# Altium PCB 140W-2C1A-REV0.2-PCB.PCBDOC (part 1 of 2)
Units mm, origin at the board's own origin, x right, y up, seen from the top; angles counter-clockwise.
Board outline 106.75 x 106.95 mm, 4 copper layers (Top Layer, MidLayer1, MidLayer2, Bottom Layer); 108 components, 173 nets, 312 pads, 723 vias.
Unrouted connection lines stored in the file: 15.
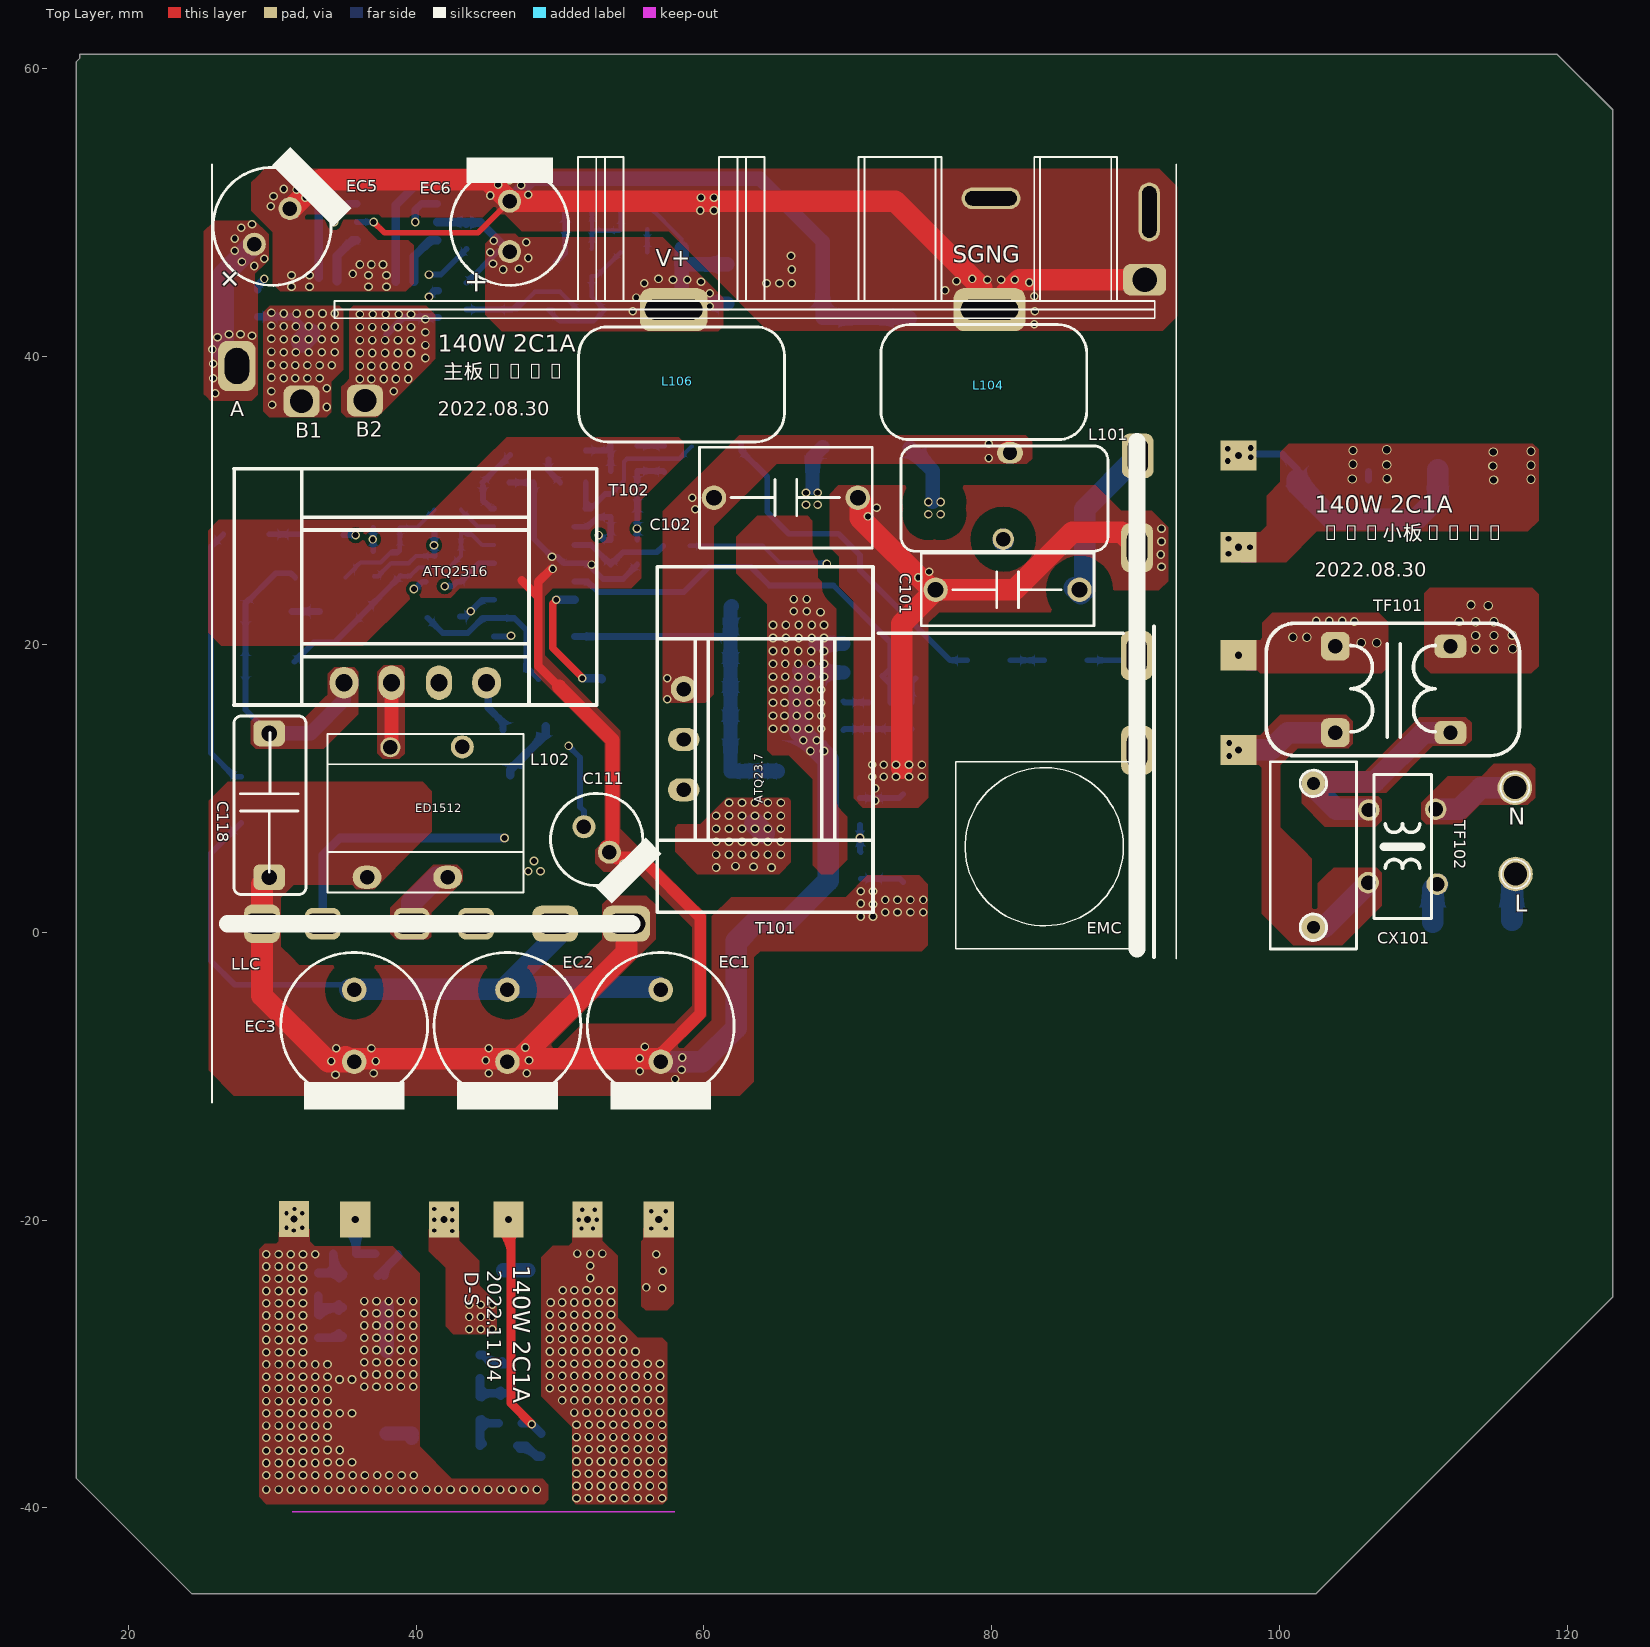
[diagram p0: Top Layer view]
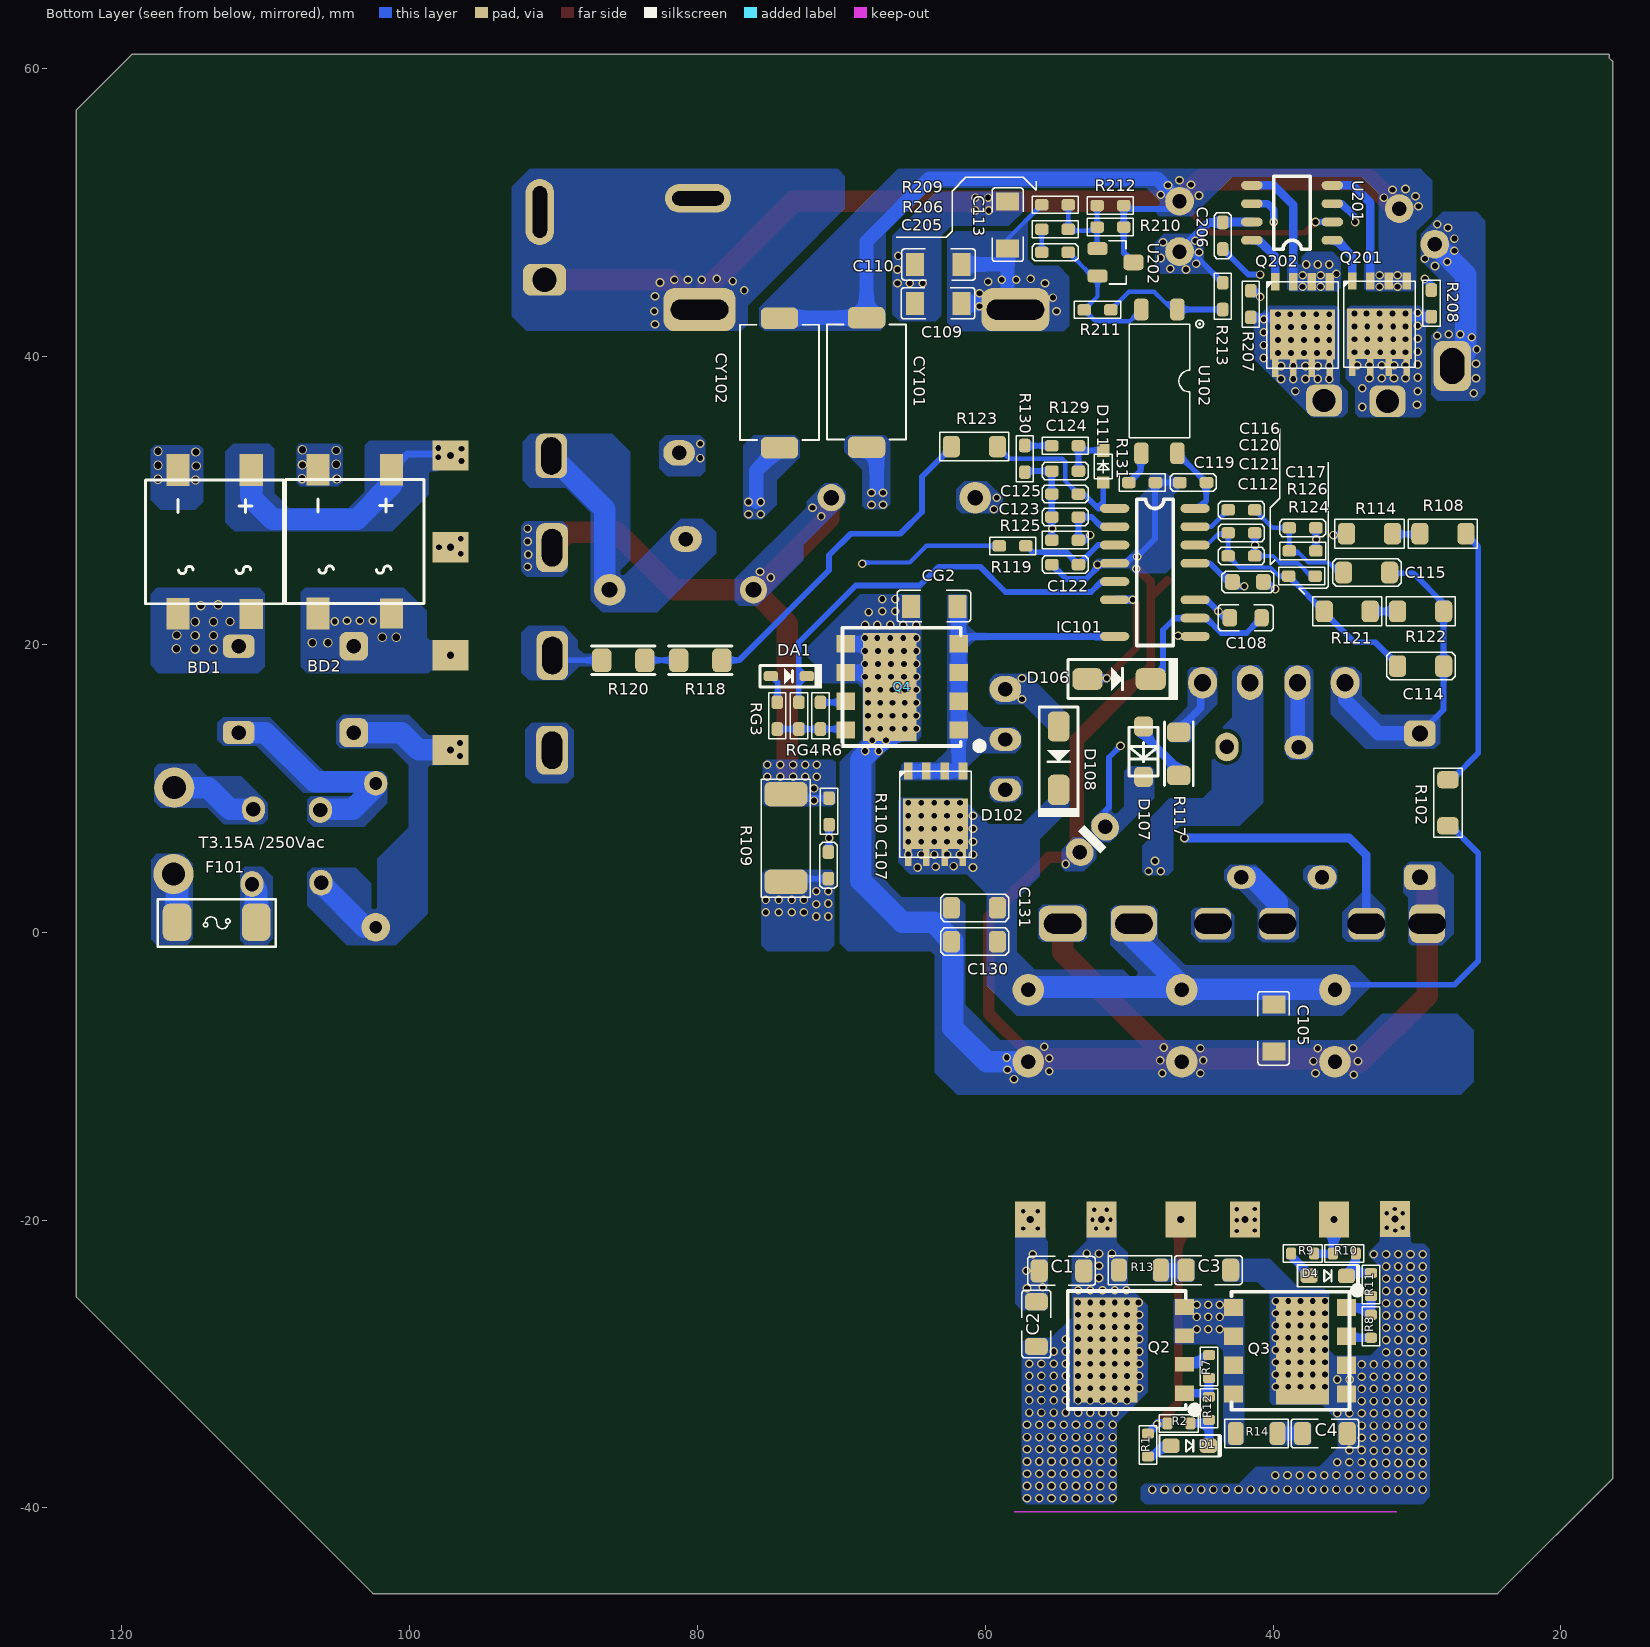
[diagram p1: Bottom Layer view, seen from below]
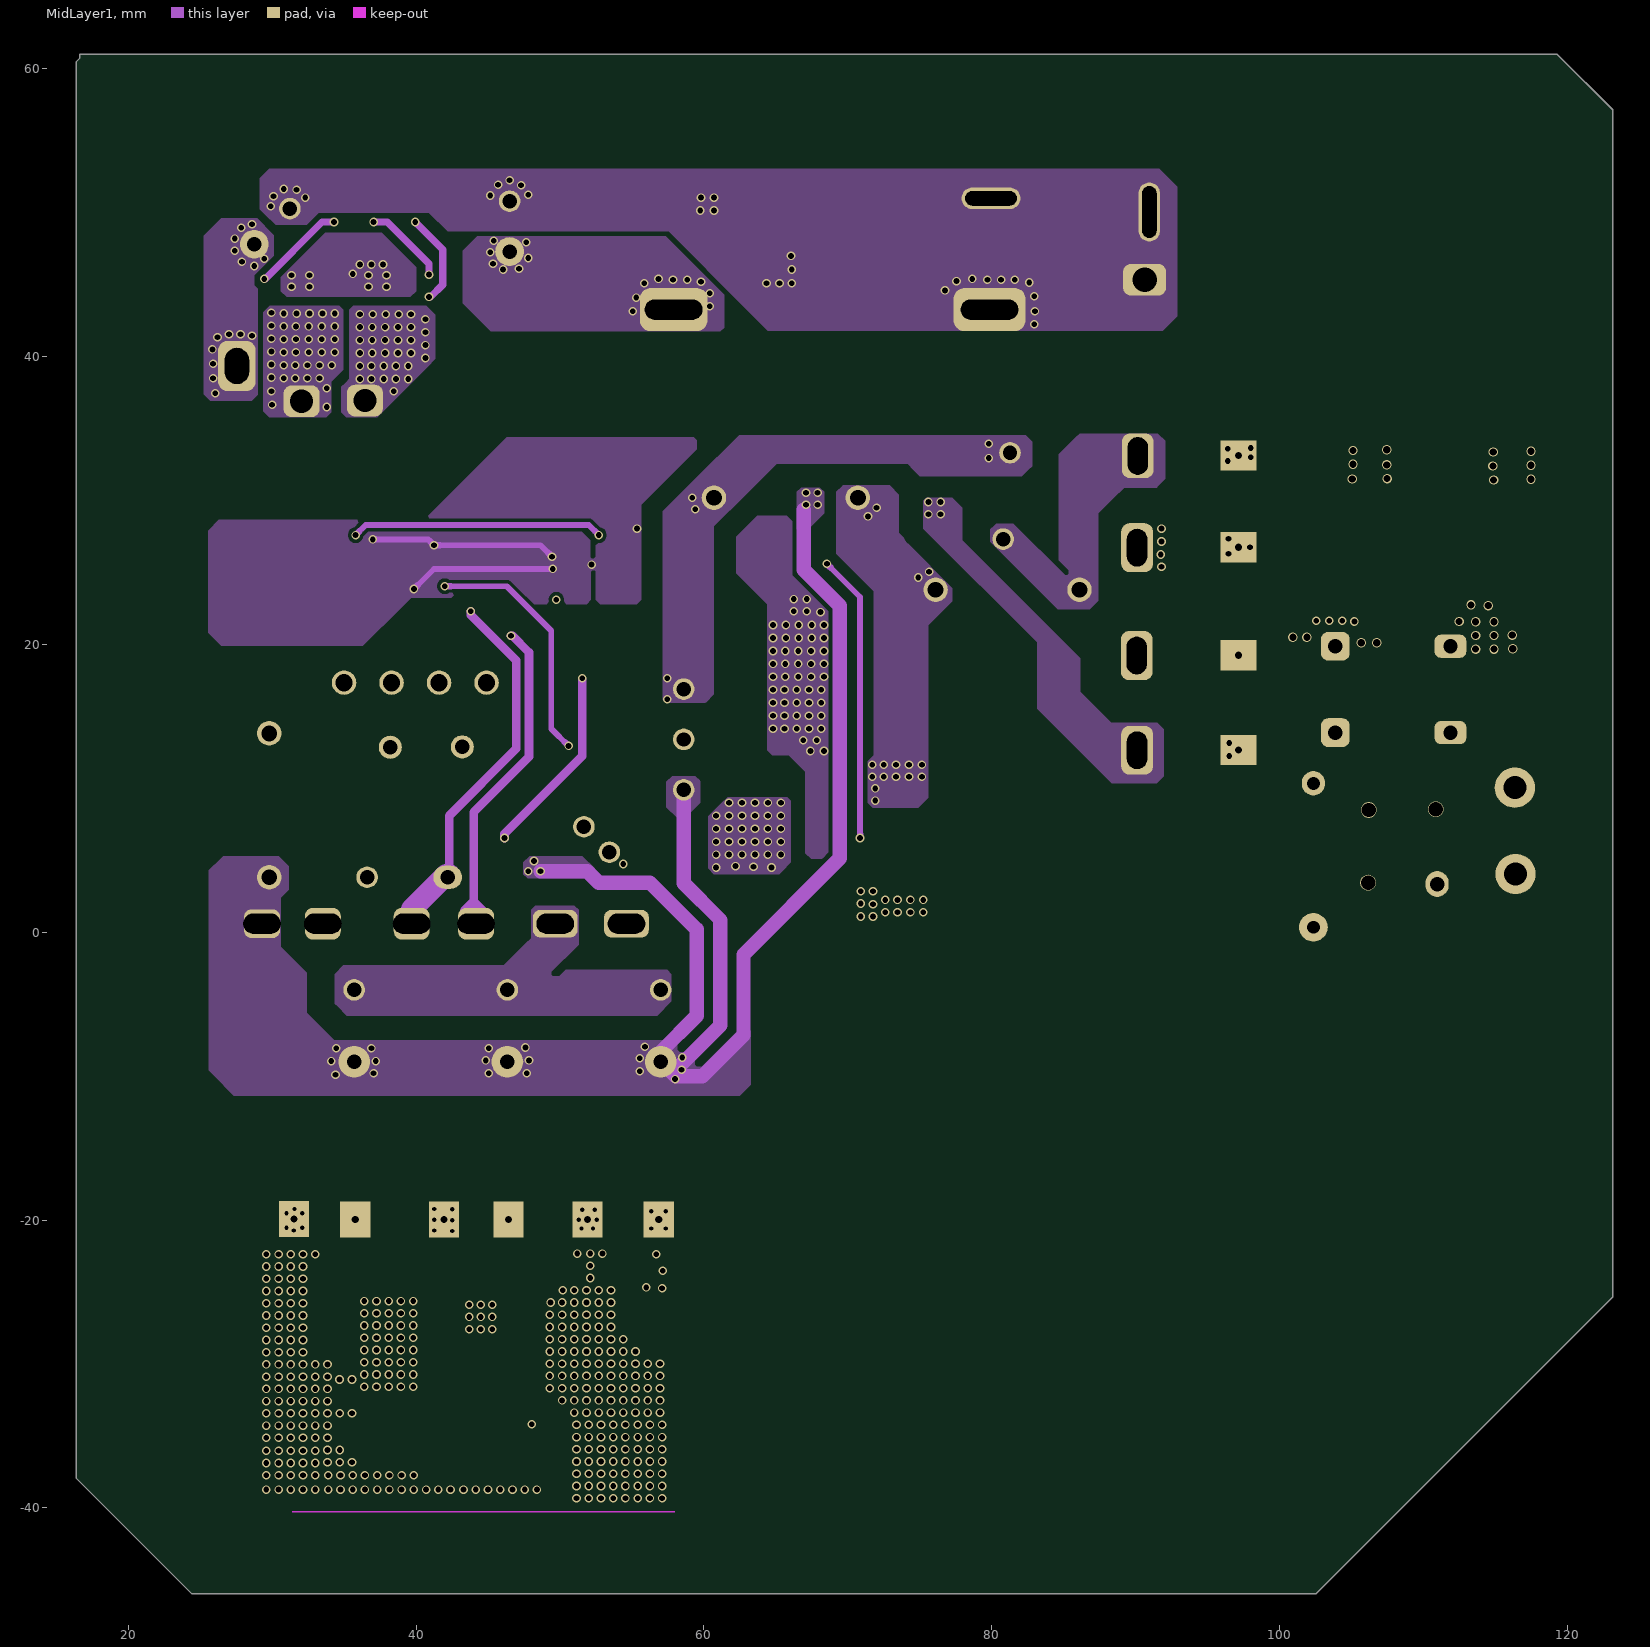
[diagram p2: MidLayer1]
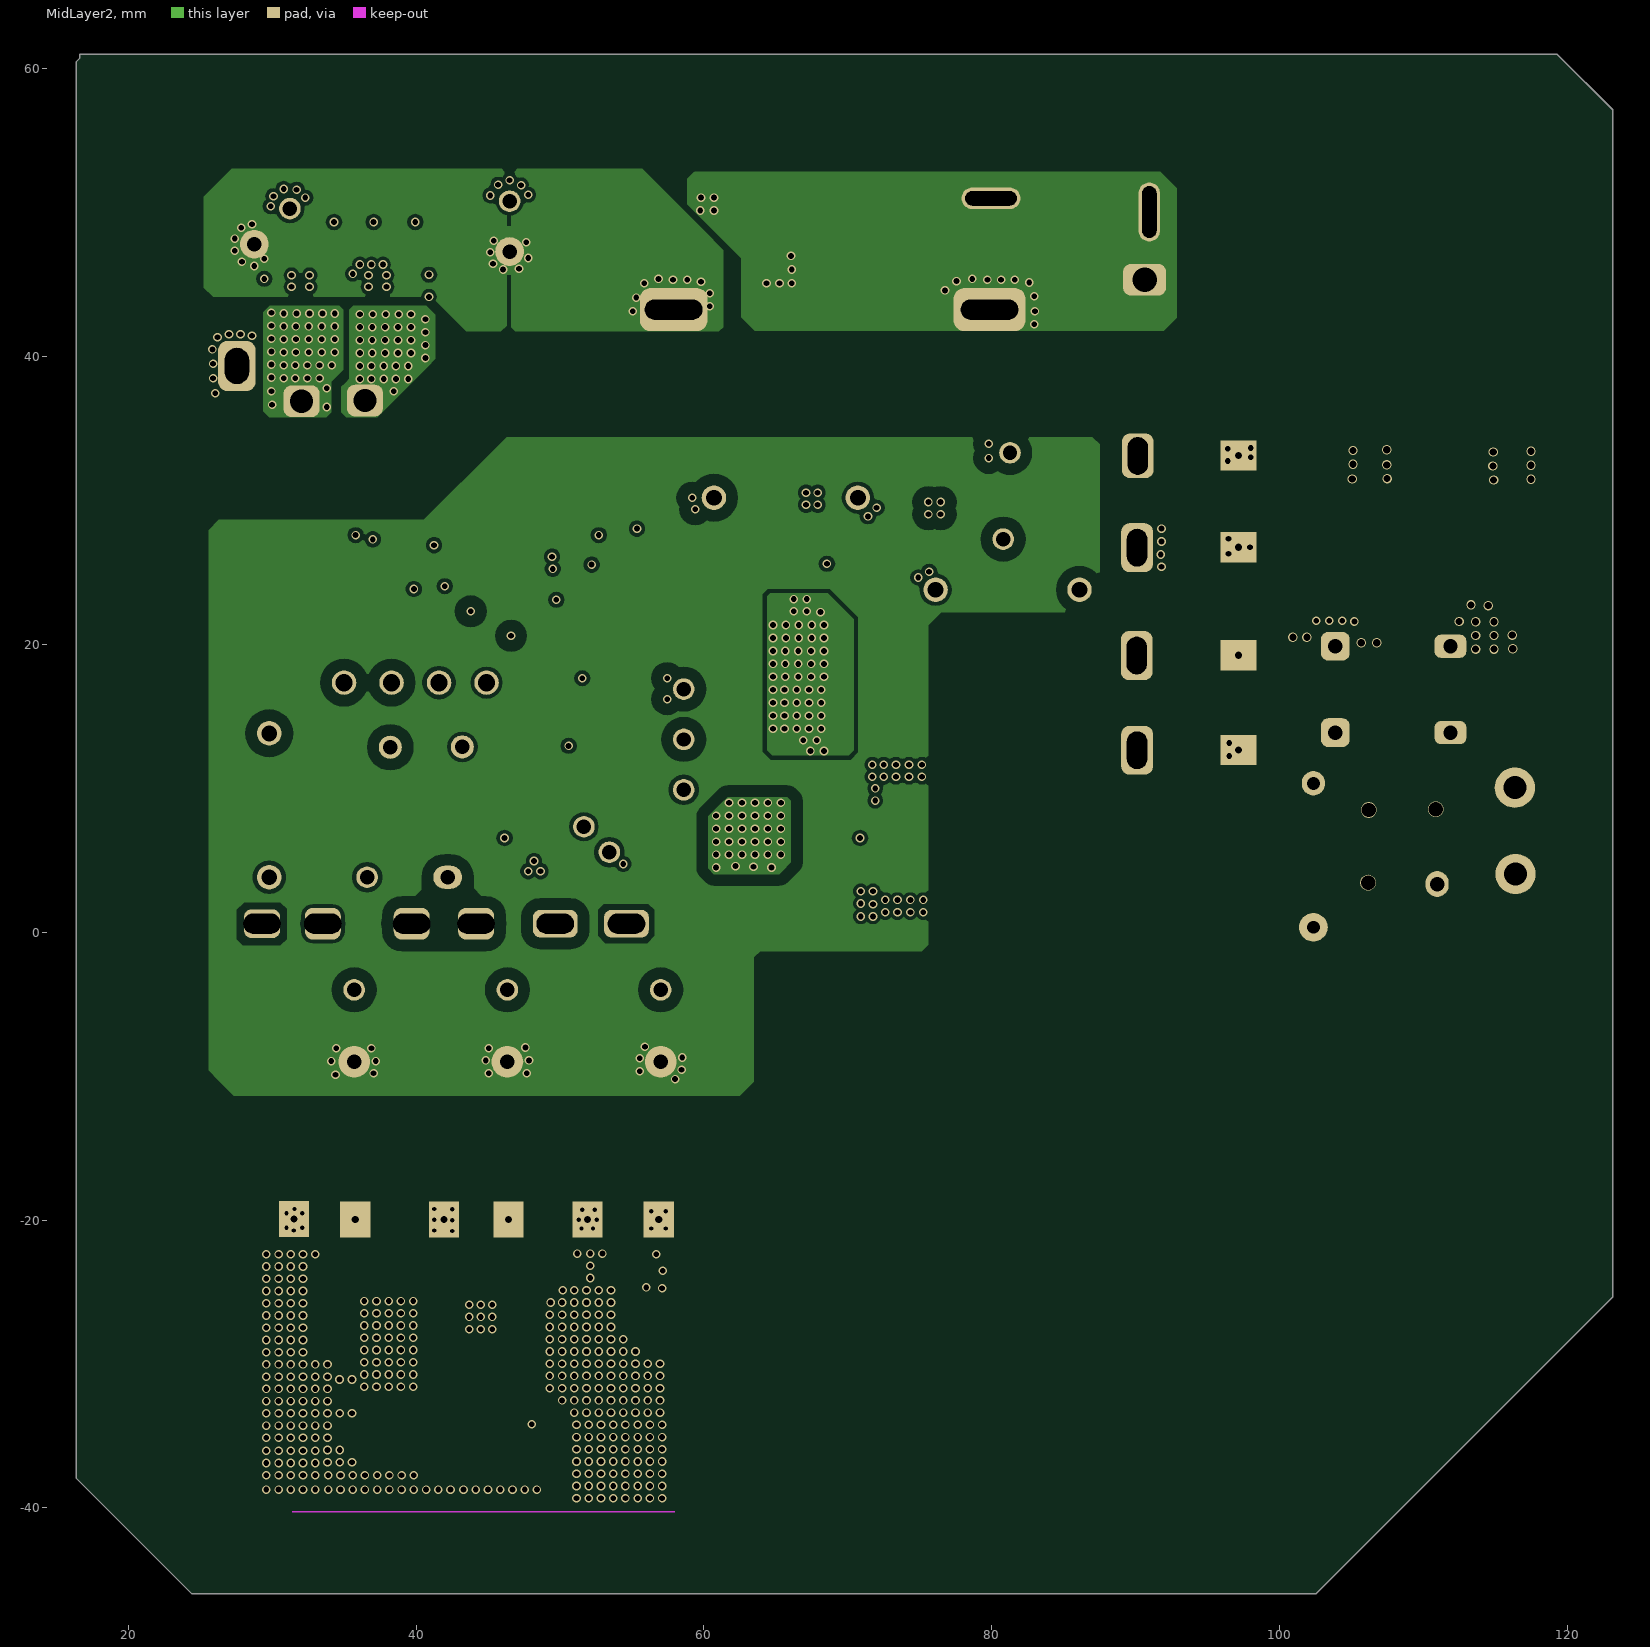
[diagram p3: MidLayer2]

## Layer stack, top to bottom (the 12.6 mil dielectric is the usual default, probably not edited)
Top Solder: solder mask 0.0102, Solder Resist, Dk 3.5
Top Layer: signal copper 0.0356
Dielectric1: core 0.32, FR-4, Dk 4.8
MidLayer1: signal copper 0.0356
Dielectric2: prepreg 0.32, FR-4, Dk 4.8
MidLayer2: signal copper 0.0356
Dielectric3: core 0.32, FR-4, Dk 4.8
Bottom Layer: signal copper 0.0356
Bottom Solder: solder mask 0.0102, Solder Resist, Dk 3.5

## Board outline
16.65,61 119.3,61 123.15,57.15 123.15,-25.35 102.55,-45.95 24.4,-45.95 16.4,-37.95 16.4,60.5 16.65,60.75
cut-out: -672.841,-265.044 -672.587,-265.044 -672.587,-264.79 -672.841,-264.79

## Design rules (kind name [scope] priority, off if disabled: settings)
Clearance Clearance_5 [InNet('NetBD101_4') vs InNet('NetCX101_2')] p1: gap=1.5
Clearance Clearance_4 [InNet('NetBD101_1') vs InNet('NetBD101_4')] p2: gap=1.5
Clearance Clearance_3 [InNet('PGND') And OnLayer('MidLayer2') vs InNetClass('New Class')] p3: gap=0.8
Clearance Clearance_1 [InNet('PGND') And OnLayer('MidLayer1') vs InNetClass('New Class')] p4: gap=0.8
Clearance [InNet('PGND') And OnLayer('Top Layer') vs InNetClass('New Class')] p5: gap=1.2
Clearance Clearance_2 [All] p6: gap=0.25
ComponentClearance [All] p1 off: gap=0.254 collisioncheckmode=3 verticalgap=0.254 showdistances=FALSE
FabricationTestpoint [(IsPad And (OnTopLayer Or OnBottomLayer))] p1: side=3 testpointundercomponent=TRUE minsize=1.016 maxsize=2.54 preferedsize=1.524 minholesize=0 maxholesize=1.016 preferedholesize=0.813 testpointgrid=0.025 allowsidetop=TRUE allowsidebottom=TRUE usegrid=TRUE gridtolerance=0
Height [All] p1 off: minheight=0 maxheight=25.4 prefheight=12.7
HoleSize [All] p1: absolutevalues=TRUE maxlimit=6 minlimit=0.4 maxpercent=80.000 minpercent=20.000
PolygonConnect [All] p1: connectstyle=Direct reliefconductorwidth=0.254 reliefentries=4 polygonreliefangle="90 Angle" airgapwidth=0.254
RoutingVias [All] p1: holewidth=0.4 width=0.7 viastyle="Through Hole" minholewidth=0.4 minwidth=0.5 maxholewidth=0.6 maxwidth=0.8
SolderMaskExpansion [All] p1: expansion=0.075
Width [All] p1: maxlimit=10 minlimit=0.2 preferedwidth=0.4 midlayer1_minwidth=0.254 midlayer2_minwidth=0.254 bottomlayer_minwidth=0.3 minimp=50.000000 maximp=50.000000 favimp=50.000000
26 further rules are at their usual default settings.

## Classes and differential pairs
net class "New Class": GATEH NetBD1 NetBD101_1 NetC101_1 NetC101_2 NetC108_1 NetC114_1 NetCX101_2 NetD103_1 NetIC101_9 NetL102_2
component class TEA2016-AP-SCH: BD101 C104 C105 C107 C108 C111 C112 C114 C115 C116 C117 C118 C119 C120 C121 C122 C123 C124 C201 C202 C203 C204 C205 C206 C207 C208 C211 CN101 CY101 D101 D103 D105 D106 D107 D109 D110 D111 D201 D202 F101 Q101 Q103 Q201 Q202 R102 R103 R105 R106 R107 R108 R109 R110 R111 R112 R113 R114 R115 R116 R117 R118 R119 R121 R122 R123 R124 R125 R126 R127 R129 R130 R131 R133 R201 R202 R203 R204 R205 R206 R208 R209 R210 R211 R212 R213 R214 R215 R216 T101 T102 TF102 U102 U103 U202 Z201
pad class "New Class": Free-00

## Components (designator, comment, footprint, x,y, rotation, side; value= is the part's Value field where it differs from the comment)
BD1 "WRLSB80M" MB30M 113.55,27.125 r90 bottom
BD2 "WRLSB80M" MB30M 103.8,27.15 r90 bottom
C1 "223M/630V" 1206CH 54.698,-23.525 r0 bottom (schematic designator C105)
C2 "223M/630V" 1206CH 56.448,-27.225 r90 bottom (schematic designator C105)
C3 "223M/630V" 1206CH 44.498,-23.475 r0 bottom (schematic designator C105)
C4 "223M/630V" 1206CH 36.398,-34.825 r180 bottom (schematic designator C105)
C101 "474/450V" XC-12X6-P10#1 81.1,23.8 r0 top
C102 "474/450V" XC-12X6-P10#2 65.7,30.2 r0 top (schematic designator C101)
C105 "223M/630V" 1206C(W)#1 39.95,-6.65 r90 bottom
C107 "473" 0603C(W) 70.9,4.65 r90 bottom
C108 "334PM/50V" 0805C(W)#1 41.9,21.85 r180 bottom
C109 "103M/50V" 1206C(W)#1 63.269,43.689 r180 bottom (schematic designator C105)
C110 "103M/50V" 1206C(W)#1 63.269,46.414 r0 bottom (schematic designator C105)
C111 "47UF/50V" EC-6.5X11-P2.5-C 52.55,6.45 r315 top
C112 "104" 0805C(W)#2 41.75,24.35 r180 bottom
C113 "103M/50V" 1206C(W)#1 58.45,49.15 r270 bottom (schematic designator C105)
C114 "1KV/33P" 1206C(W)#2 29.75,18.5 r0 bottom
C115 "1KV/102PK" 1206C(W)#2 33.5,25 r0 bottom
C116 "222PK/50V" 0603C(W) 42.2,29.35 r0 bottom
C117 "103PK/50V" 0603C(W) 37.95,28.1 r0 bottom
C118 "MMKP82/333J/630V" MC-15.5X6.5-P12.5 29.847,7.723 r90 top
C119 "NC" 0603C(W) 45.55,31.25 r0 bottom
C120 "103" 0603C(W) 42.2,27.75 r0 bottom
C121 "102" 0603C(W) 42.2,26.15 r0 bottom
C122 "1nF" 0603C(W) 54.45,25.55 r180 bottom
C123 "561PJ" 0603C(W) 54.45,28.85 r180 bottom
C124 "561" 0603C(W) 54.45,32.05 r180 bottom
C125 "100PJ/50V" 0603C(W) 54.45,30.45 r180 bottom (schematic designator C124)
C130 "223M/630V" 1206C(W)#2 60.75,-0.65 r0 bottom (schematic designator C105)
C131 "223M/630V" 1206C(W)#2 60.75,1.7 r0 bottom (schematic designator C105)
C205 "104PM" 0603C(W) 55.15,47.25 r0 bottom
C206 "104PM" 0603C(W) 43.5,48.4 r270 bottom (schematic designator C205)
CG2 "223M/630V" 1206C(W)#1 63.55,22.65 r180 bottom (schematic designator C105)
CX101 "474PM/275V" "CX-5*13  P=10mm" 102.35,5.35 r270 top
CY101 "1nF/400Vac" "1808 Y-Cap" 68.647,38.248 r270 bottom (schematic designator CY3)
CY102 "1nF/400Vac" "1808 Y-Cap" 74.697,38.223 r270 bottom (schematic designator CY3)
D1 "NC" 323 45.798,-35.675 r0 bottom (schematic designator D4)
D4 "NC" 323 36.198,-23.875 r0 bottom
D102 "600V/4A SIC" DFN5*6-8L 61.55,11.2 r0 bottom
D106 "RS2M" SMD-(DO-214AC/SMA)(H) 50.7,17.6 r180 bottom (schematic designator D2)
D107 "FR107" SOD-80 49,12.55 r270 bottom
D108 "S3M" SMD-(DO-214AC/SMA)(H) 54.9,12.1 r270 bottom (schematic designator D106)
D111 "1N4148(0805)" SOD-323 51.8,31.25 r180 bottom (schematic designator D4)
DA1 "1N4148" SMD-(SOD-323)(H) 73.65,17.8 r180 bottom
EC1 "22UF/450V 8X17" EC-10X18-P5-C 57,-6.5 r270 top (schematic designator CD3)
EC2 "450V/22UF 10*17" EC-10X18-P5-C 46.35,-6.5 r270 top
EC3 "22UF/450V 8X17" EC-10X18-P5-C 35.7,-6.5 r270 top (schematic designator CD3)
EC5 "Comment" EC-8X12-P3.5-C 30,49.05 r45 top
EC6 "Comment" EC-8X12-P3.5-C 46.5,49.05 r90 top
EMC "Comment" 无桥整流 90.1,-0.275 r90 top locked
F101 "T3.15A /250Vac" F-6125 113.4,0.7 r0 bottom
IC101 "TEA2016/SOP-16" SO-16 51,29.45 r180 bottom (schematic designator U1)
L101 "200UH" L10*6*5#1 80.622,30.548 r270 top
L102 "ED1512" ED1512 40.7,3.825 r90 top locked
L104 "T12/6/5/20UH" L10*6*5#2 79.75,38 r90 top
L106 "T12/6/5/20UH" L10*6*5#2 58.15,38.3 r270 top
LLC "Comment" LLC 54.622,0.598 r180 top locked
Q2 "Comment" IPL60R365P7-Cascode-DFN8X8 48.898,-29.025 r90 bottom
Q3 "Comment" "Cascode-DFN8X8 - new" 38.848,-29.075 r270 bottom
Q4 "Comment" "Cascode-DFN8X8 - new" 65.75,17.05 r90 bottom
Q201 "60V/4mR" DFN5*6-8L 30.7,45.25 r0 bottom
Q202 "60V/4mR" DFN5*6-8L 36.05,45.2 r0 bottom
R1 "NC" 0603RH 48.698,-35.625 r90 bottom (schematic designator R103)
R2 "300R" 0603RH 46.548,-34.125 r0 bottom (schematic designator R105)
R6 "300R" 0603R 71.45,15.05 r270 bottom (schematic designator R105)
R7 "10K" 0603RH 44.448,-30.175 r270 bottom (schematic designator R133)
R8 "10K" 0603RH 33.198,-27.375 r90 bottom (schematic designator R133)
R9 "NC" 0603RH 37.948,-22.325 r180 bottom (schematic designator R111)
R10 "300R" 0603RH 35.048,-22.325 r0 bottom (schematic designator R112)
R11 "300R" 0603RH 33.198,-24.475 r90 bottom (schematic designator R112)
R12 "300R" 0603RH 44.448,-33.075 r270 bottom (schematic designator R112)
R13 "300R" 1206RH 49.248,-23.475 r180 bottom (schematic designator R112)
R14 "300R" 1206RH 41.148,-34.825 r180 bottom (schematic designator R112)
R102 "750K" 1206(W) 27.85,9 r270 bottom
R108 "7.5M" 1206(W) 28.2,27.7 r180 bottom
R109 "0.068R" 2512(W) 73.85,6.55 r90 bottom
R110 "2.7R" 0603(W) 70.85,8.4 r270 bottom
R114 "7.5M" 1206(W) 33.3,27.7 r180 bottom
R117 "4.7R" 1206 46.55,13.9 r270 bottom
R118 "10M" 1206 78.3,18.9 r0 bottom
R119 "100R" 0603(W) 58.1,26.85 r180 bottom
R120 "10M" 1206 83.65,18.9 r0 bottom (schematic designator R118)
R121 "1M5" 1206(W) 34.85,22.3 r0 bottom
R122 "1M3" 1206(W) 29.75,22.3 r0 bottom
R123 "10M" 1206(W) 60.75,33.75 r180 bottom
R124 "20K" 0603(W) 38,24.75 r0 bottom
R125 "1K" 0603(W) 54.45,27.25 r180 bottom
R126 "13R3" 0603(W) 37.95,26.5 r0 bottom
R129 "20K" 0603(W) 54.45,33.8 r180 bottom
R130 "NTC/100K" 0603(W) 57.25,32.9 r270 bottom
R131 "1K" 0603(W) 49.1,31.25 r0 bottom
R206 "47K" 0603R 55.15,48.85 r180 bottom
R207 "20R" 0603R 41.55,43.65 r90 bottom (schematic designator R206)
R208 "20R" 0603R 29,43.7 r90 bottom (schematic designator R206)
R209 "68K 1%" 0603R 55.15,50.55 r180 bottom
R210 "680K 1%" 0603R 51.3,49 r0 bottom
R211 "1K" 0603R 52.2,43.25 r180 bottom
R212 "9K31 1%" 0603R 51.3,50.5 r0 bottom
R213 "3K" 0603R 43.5,44.2 r90 bottom
RG3 "10R" 0603R 74.45,15.05 r90 bottom (schematic designator R22)
RG4 "390R" 0603R 72.95,15.05 r90 bottom (schematic designator R22)
T101 "ATQ23.7" ATQ23.7 64.25,13.4 r0 top locked
T102 "ATQ2516" ATQ25 34.997,17.348 r0 top locked
TF101 "TD1212-8MH" TD-1212-15MH 107.875,16.875 r0 top
TF102 "T9/5/3/600UH/0.5/8TS" 9*5*3 108.55,5.95 r270 top
U102 "CT1019" W_SO-4(P10)__EL1019 47.9,38.25 r270 bottom
U201 "TEA1995" SO-8 35.9,48.1 r0 bottom
U202 "Comment" SOT-23 50.95,46.55 r270 bottom

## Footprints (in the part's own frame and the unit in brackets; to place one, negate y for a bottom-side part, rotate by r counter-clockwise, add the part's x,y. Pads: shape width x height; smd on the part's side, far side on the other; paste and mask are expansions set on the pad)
9*5*3 [mm]
  round 1.5 / inner round 1.1 / far side oval 1.8x1.6 hole 1: 1(-2.6,2.3) 3(2.5,-2.4) 4(-2.55,-2.35)
  round 1.5 / inner oval 1.8x1.6 / far side oval 1.8x1.6 hole 1: 2(2.6,2.4)
  silkscreen extent -5,-2 5,2
323 [mm]
  rrect50% 1.2x1 smd mask+0.03: 1(1.3,0) 2(-1.3,0)
  silkscreen extent -2.25,-0.75 2.1,0.75, body extent -1.3,-0.65 1.3,0.65, height 1
0603(W) [mm]
  rrect50% 0.95x0.8 smd mask+0.03: 1(-0.925,0) 2(0.925,0)
  silkscreen extent -1.6,-0.6 1.6,0.6, body extent -0.77,-0.42 0.78,0.43, height 0.45
0603C(W) [mm]
  rrect50% 0.95x0.8 smd mask+0.03: 1(-0.925,0) 2(0.925,0)
  silkscreen extent -1.6,-0.6 1.6,0.6, body extent -0.8,-0.4 0.8,0.4, height 0.8
0603R [mm]
  rrect50% 0.95x0.8 smd mask+0.03: 1(-0.925,0) 2(0.925,0)
  silkscreen extent -1.6,-0.6 1.6,0.6, body extent -0.77,-0.42 0.78,0.43, height 0.45
0603RH [mm]
  rrect50% 0.7x0.85 smd mask+0.03: 1(-0.8,0) 2(0.8,0)
  silkscreen extent -1.35,-0.6 1.35,0.6, body extent -0.77,-0.42 0.78,0.43, height 0.45
0805C(W)#1 [mm]
  rrect50% 1x1.2 smd: 1(-1.1,0) 2(1.1,0)
  silkscreen extent -1.9,-0.9 1.9,0.9
0805C(W)#2 [mm]
  rrect50% 1.05x1.1 smd mask+0.03: 1(-1.075,0) 2(1.075,0)
  silkscreen extent -1.8,-0.75 1.8,0.75, body extent -1,-0.62 1,0.63, height 0.6
1206 [mm]
  rrect50% 1.35x1.65 smd: 1(0,0) 2(3,0)
  silkscreen extent -0.7,-1 3.7,1
1206(W) [mm]
  rrect50% 1.2x1.5 smd mask+0.03: 1(-1.6,0) 2(1.6,0)
  silkscreen extent -2.4,-1 2.4,1, body extent -1.6,-0.8 1.6,0.8, height 0.55
1206C(W)#1 [mm]
  rect 1.25x1.6 smd: 1(-1.625,0) 2(1.625,0)
  silkscreen extent -2.58,-1.07 2.53,1.1
1206C(W)#2 [mm]
  rrect50% 1.2x1.5 smd mask+0.03: 1(-1.6,0) 2(1.6,0)
  silkscreen extent -2.4,-0.95 2.35,0.95, body extent -1.6,-0.8 1.6,0.8, height 0.79
1206CH [mm]
  rrect50% 1.2x1.6 smd mask+0.03: 1(-1.55,0) 2(1.55,0)
  silkscreen extent -2.35,-1 2.35,1, body extent -1.6,-0.8 1.6,0.8, height 0.79
1206RH [mm]
  rrect50% 1.1x1.6 smd mask+0.03: 1(-1.45,0) 2(1.45,0)
  silkscreen extent -2.2,-1 2.2,1, body extent -1.6,-0.8 1.6,0.8, height 0.55
"1808 Y-Cap" [mm]
  rrect50% 1.5x2.6 smd: 1(-4.45,0.4) 2(4.55,0.4)
  silkscreen extent -3.99,-2.35 4.01,3.15
2512(W) [mm]
  rrect50% 1.7x3 smd mask+0.03: 1(-3.05,0) 2(3.05,0)
  silkscreen extent -4.1,-1.7 4.1,1.7, body extent -3.05,-1.6 3.35,1.6, height 0.6
ATQ23.7 [mm]
  round 1.8 / inner round 1.5 / far side oval 2.2x1.8 hole 1: 1(-5.65,3.5)
  oval 2.2x1.6 / inner round 1.5 / far side oval 2.2x1.6 hole 1: 2(-5.65,0) 3(-5.65,-3.5)
  silkscreen extent -7.5,-12 7.5,12
ATQ25 [mm]
  oval 2x2.2 / inner round 1.7 / far side oval 2x2.2 hole 1.2: 1(0,0) 4(9.9,0)
  oval 1.8x2.4 / inner round 1.7 / far side oval 1.8x2.4 hole 1.2: 2(3.3,0) 3(6.6,0)
  silkscreen extent -7.65,-1.55 17.55,14.85
"Cascode-DFN8X8 - new" [mm]
  rect 1.2x1.3 smd: D(-3,-3.9) D(-1,-3.9) D(1,-3.9) D(3,-3.9) G(-3,3.95) S(-1,3.95) S(1,3.95) S(3,3.95)
  rect 7.5x3.7 smd: S(0,0.887)
  silkscreen extent -4.45,-4.04 4.1,4.95
"CX-5*13  P=10mm" [mm]
  oval 1.7x1.6 hole 0.9: 1(-5,0)
  round 2 hole 0.9: 2(5,0)
  silkscreen extent -6.5,-3 6.5,3
DFN5*6-8L [mm]
  rect 0.6x1.2 smd: 1S(0,0) 2S(1.27,0) 3S(2.54,0) 4G(3.81,0)
  rect 0.45x1.2 smd: 5D(3.81,6) 6D(2.54,6) 7D(1.27,6) 8D(0,6)
  rect 4.5x3.5 smd: 9D(1.9,3.66)
  silkscreen extent -0.59,0 4.41,6
EC-6.5X11-P2.5-C [mm]
  round 1.6 / inner round 1.5 / far side oval 1.8x2 hole 1 mask+0.03: 1(-1.25,0) 2(1.25,0)
  silkscreen extent -3.2,-3.2 3.9,3.2, body extent -3.18,-3.18 3.18,3.18, height 11.33
EC-8X12-P3.5-C [mm]
  round 1.6 / inner round 2 / far side round 2 hole 1 mask+0.03: 1(-1.75,0)
  round 1.6 / inner round 1.5 / far side round 2 hole 1 mask+0.03: 2(1.75,0)
  silkscreen extent -4.1,-4.1 4.8,4.1, body extent -4.1,-4.1 4.1,4.1, height 13.1
EC-10X18-P5-C [mm]
  round 1.7 / inner round 1.5 / far side round 2.2 hole 1 mask+0.03: 1(-2.5,0)
  round 1.7 / inner round 2.2 / far side round 2.2 hole 1 mask+0.03: 2(2.5,0)
  silkscreen extent -5.1,-5.1 5.8,5.1, body extent -5.1,-5.1 5.1,5.1, height 19.05
ED1512 [mm]
  oval 1.6x2 hole 1: 1(0,-1.5)
  oval 1.6x2 / inner round 1.5 / far side oval 1.6x2 hole 1: 2(0,4.1)
  round 1.4 / inner round 1.6 / far side oval 1.6x2 hole 1: 3(9.033,2.487)
  round 1.6 / inner round 1.6 / far side oval 2x1.6 hole 1: 4(9.058,-2.513)
  silkscreen extent -1.05,-6.76 9.95,6.84
F-6125 [mm]
  rrect50% 2x2.6 smd mask+0.03: 1(-2.75,0) 2(2.75,0)
  silkscreen extent -4.1,-1.6 4.1,1.7
IPL60R365P7-Cascode-DFN8X8 [mm]
  rect 7.3x4.45 smd: D(0,2.737)
  rect 1.1x1.3 smd: G(-3,-2.737) S(3,-2.737)
  rect 1x1.3 smd: S(-1,-2.737) S(1,-2.737)
  silkscreen extent -4.4,-3.7 4.1,5.36, body extent -4.05,-2.8 4.05,5.3, height 1.1
L10*6*5#1 [mm]
  round 1.5 / inner round 1.5 / far side oval 1.8x2.2 hole 1: 0(3.229,0.175)
  oval 1.5x1.8 / inner round 1.5 / far side oval 1.8x2.2 hole 1: 1(-2.771,0.65)
  silkscreen extent -3.25,-6.93 4.08,7.45
L10*6*5#2 [mm]
  silkscreen extent -3.77,-6.85 4.23,7.45
LLC [mm]
  rrect50% 3.3x2.5 / inner rrect50% 3.1x1.9 / far side rrect50% 3.3x2.5 hole 1.4 slot 2.6 at 0 deg: 1(0,0)
  rrect50% 3.2x2.5 / inner rrect50% 3.1x1.9 / far side rrect50% 3.2x2.5 hole 1.4 slot 2.6 at 0 deg: 2(4.95,0)
  rrect50% 2.5x2.2 hole 1.4 slot 2.6 at 0 deg: 3(10.45,0) 4(14.925,0) 5(21.1,0)
  rrect50% 2.5x2.7 / inner rrect50% 2.5x2 / far side rrect50% 2.5x2.7 hole 1.4 slot 2.6 at 0 deg: 6(25.325,0)
  silkscreen extent -0.38,0 27.72,0
MB30M [mm]
  rect 2.2x1.6 smd: 1(-5,2.55) 3(5,-2.55) 4(5,2.55)
  rect 2.1x1.6 smd: 2(-5,-2.55)
  silkscreen extent -4.3,-4.8 4.3,4.8
MC-15.5X6.5-P12.5 [mm]
  rrect50% 1.8x2.2 / inner round 1.7 / far side rrect50% 1.8x2.2 hole 1.1 mask+0.03: 1(-3.9,0.05) 2(6.1,0.05)
  silkscreen extent -5.1,-2.5 7.3,2.5
SMD-(DO-214AC/SMA)(H) [mm]
  rrect50% 2.1x1.5 smd mask+0.03: 1(-2.2,0) 2(2.2,0)
  silkscreen extent -3.55,-1.45 4.1,1.45, body extent -2.3,-1.35 2.3,1.35, height 2.4
SMD-(SOD-323)(H) [mm]
  rrect50% 1x0.7 smd mask+0.03: 1(-1.25,0) 2(1.25,0)
  silkscreen extent -2,-0.85 2.3,0.85, body extent -1.3,-0.65 1.3,0.65, height 1
SO-8 [mm]
  oval 1.5x0.61 smd: 1GDB(-0.014,0.012) 2GND(-0.014,-1.257) 3DSB(-0.014,-2.527) 4SSB(-0.014,-3.797) 5SSA(5.573,-3.797) 6DSA(5.573,-2.527) 7VCC(5.574,-1.257) 8GDA(5.574,0.013)
  silkscreen extent 1.51,-4.43 4.05,0.65
SO-16 [mil]
  oval 80x24 smd: 1(-0.28,0) 2(-0.28,-50) 3(-0.28,-100) 4(-0.28,-150) 5(-0.28,-200) 6(-0.28,-250) 8(-0.28,-350) 9(219.72,-350) 10(219.72,-300) 11(219.72,-250) 13(219.72,-150) 14(219.72,-100) 15(219.72,-50) 16(219.72,0)
  oval 80x24 on Mech13: 7(-0.28,-300) 12(219.72,-200)
  silkscreen extent 60,-375 160,25, body extent -6,-371 230,23, height 72
SOD-80 [mm]
  rrect50% 1.4x1.3 smd: 1(-1.75,0) 2(1.75,-0.001)
  silkscreen extent -1.7,-1 1.7,1
SOD-323 [mm]
  rect 0.85x0.85 smd: A(0,0)
  rect 0.85x0.9 smd: K(0,2.23)
  silkscreen extent -0.63,0.26 0.63,1.97
SOT-23 [mm]
  rrect50% 0.9x1.4 smd mask+0.03: 1(-0.95,-1.25) 3(0.95,-1.25)
  rrect50% 1.1x1.4 smd mask+0.03: 2(0,1.25)
  silkscreen extent -1.5,-0.45 1.5,0.75, body extent -1.45,-1.4 1.45,1.4, height 1.2
TD-1212-15MH [mm]
  rrect50% 2.2x1.6 hole 1: 0(4,3) 1(4,-3)
  rrect50% 2x2 hole 1: 2(-4,-3) 3(-4,3)
  silkscreen extent -8.8,-4.6 8.8,4.6
W_SO-4(P10)__EL1019 [mm]
  rrect50% 1.5x1 smd: 1(-5.025,1.25) 2(-5.025,-1.25) 3(4.975,-1.251) 4(4.975,1.25)
  silkscreen extent -4.29,-2.1 3.9,3.07
XC-12X6-P10#1 [mm]
  round 1.7 / inner round 1.7 / far side round 1.9 hole 1.1 mask+0.03: 1(-5,0)
  round 1.7 / inner round 1.7 / far side round 2.2 hole 1.1 mask+0.03: 2(5,0)
  silkscreen extent -6,-2.5 6,2.55
XC-12X6-P10#2 [mm]
  round 1.7 / inner round 1.7 / far side round 2.2 hole 1.1 mask+0.03: 1(-5,0)
  round 1.7 / inner round 1.7 / far side round 1.9 hole 1.1 mask+0.03: 2(5,0)
  silkscreen extent -6,-3.5 6,3.5
无桥整流 [mm]
  rrect50% 3.4x2.2 hole 1.4 slot 2.6 at 0 deg: 3(12.925,0) 4(19.5,0.025) 5(27,0)
  rrect50% 3.1x2.2 hole 1.4 slot 2.6 at 0 deg: 6(33.375,-0.05)
  silkscreen extent -0.87,0 34.37,11.95

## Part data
C1 C2 C3 C4 C105 C107 C108 C109 C110 C112 C113 C114 C115 C116 C117 C118 C119 C120 C121 C122 C123 C124 C125 C130 C131 C205 C206 CG2: library part Cap, "Capacitor"
C101 C102: library part CX, "CX"
CY101 CY102: library part Cap
D1 D4 D111: library part D
D106: library part Diode
D107 D108: library part Diode, "Default Diode"
EC1 EC3: library part CAP-E, "电解电容"
IC101: library part TEA1755T/SOP-16_1, "贴片IC"
R1 R2 R6 R7 R8 R9 R10 R11 R12 R13 R14 R102 R108 R109 R110 R114 R117 R118 R119 R120 R121 R122 R123 R124 R125 R126 R129 R131 R206 R207 R208 R209 R210 R211 R212 R213: library part Res2, "Resistor"
R130: library part "Res Adj1", "Variable Resistor"
RG3 RG4: library part 1/8WR

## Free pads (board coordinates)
  oval 4.1x1.5 / inner oval 4.1x1.5 / far side oval 4.6x2 hole 1 slot 3.6 at 0 deg: 0(79.95,51)
  rrect50% 3x2.2 hole 1.7: 0(90.625,45.342)
  oval 1.5x4.1 / inner oval 1.5x4.1 / far side oval 2x4.6 hole 1 slot 3.6 at 90 deg: 0(90.95,50.05)
  round 2.4 / inner round 2.8 / far side round 2.8 hole 1.6: 0(116.35,10.05) 0(116.4,4.05)
  rect 2.1x2.5 hole 0.5: 2(31.52,-19.925) 2(35.77,-19.95) 2(41.945,-19.95) 2(46.42,-19.95) 2(51.92,-19.95) 2(56.87,-19.95)
  rrect50% 4.7x3 hole 1.4 slot 4 at 0 deg: 2(57.9,43.267)
  rrect50% 5x3 hole 1.4 slot 4 at 0 deg: 2(79.85,43.267)
  rect 2.5x2.1 hole 0.5: 2(97.15,12.675) 2(97.15,19.25) 2(97.15,26.75) 2(97.15,33.125)
  rrect50% 2.6x3.5 hole 1.7 slot 2.5 at 90 deg: 3(27.55,39.35)
  rrect50% 2.5x2.2 hole 1.6: 3(32.05,36.9) 3(36.45,36.95)

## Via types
v1: diameter 0.6, hole 0.4, Top Layer to Bottom Layer, tented both sides, 674 vias
v2: diameter 0.65, hole 0.5, Top Layer to Bottom Layer, 27 vias
v3: diameter 0.5, hole 0.3, Top Layer to Bottom Layer, 22 vias

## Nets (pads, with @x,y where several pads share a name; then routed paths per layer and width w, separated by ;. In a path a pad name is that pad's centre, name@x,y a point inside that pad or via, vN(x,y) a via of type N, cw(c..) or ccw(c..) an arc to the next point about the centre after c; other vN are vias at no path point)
001: 
002: 
003: 
004: 
005: 
006: 
007: 
111: R118.2 R120.1 | length 2.4
  Bottom Layer w0.4: R118.2@81.3,18.9 R120.1@83.65,18.9
112: 
113: C3.2 R13.2 | length 1.7
  Bottom Layer w1: C3.2@46.048,-23.475 R13.2@47.798,-23.475
115: C4.1 R14.2 | length 1.8
  Bottom Layer w1: C4.1@37.948,-34.825 R14.2@39.698,-34.825
+20V: C109.2 C110.1 C113.2 C206.1 EC5.1 EC6.1 pad.2@57.9,43.267 pad.3@27.55,39.35 R209.1 R213.2 U201.7VCC | length 35.1
  MidLayer2 w1.5: pad.2@57.9,43.267 pad.2@57.9,43.7
  Bottom Layer w0.3: R209.1@56.075,50.55 58.45,48.175 C113.2@58.45,47.525
  Bottom Layer w0.4: R213.2@43.5,45.125 45.675,47.3 EC6.1@46.5,47.3
  Bottom Layer w0.6: U201.7VCC@41.474,49.357 43.368,49.357 C206.1@43.5,49.225 ; C206.1@43.5,49.325 44.475,49.325 EC6.1@46.5,47.3
  Bottom Layer w1: pad.2@57.9,43.267 pad.2@58.322,43.689 ; C113.2@58.45,47.525 58.45,46.3 ; C109.2@61.644,43.689 pad.2@58.322,43.689 ; C110.1@61.644,46.414 58.564,46.414 58.45,46.3 ; pad.2@58.322,43.689 58.45,43.817 58.45,46.3
  Bottom Layer w1.5: pad.3@27.55,39.35 26.6,40.35 26.6,45.7 28.713,47.813 EC5.1@28.763,47.813
  other v1: 26.05,37.45 25.9,38.5 25.9,39.5 25.85,40.5 26.2,41.35 28.6,41.45 27,41.55 27.8,41.55 55.05,43.15 60.4,43.5 55.3,44.1 60.4,44.4 55.85,45.1 59.8,45.2 57.85,45.35 58.85,45.35 56.85,45.4 46.05,46.05 47.15,46.1 28.75,46.3 45.35,46.45 27.9,46.6 29.45,46.8 47.8,46.85 45.15,47.25 27.4,47.35 47.65,47.95 45.4,48.05 27.4,48.2 27.85,48.95 28.6,49.2
C204-1: 
C206-1: 
CSNA: 
CSPA: 
CY3_2: 
CY101-1: 
G1: Q2.G R7.2 R12.1 | length 5.7
  Bottom Layer w0.6: R7.2@44.448,-30.975 44.448,-31.675 ; R12.1@44.558,-32.31 cw(c45.247,-32.999) 45.247,-32.025 ; 45.198,-32.025 R12.1@44.798,-32.025 ; Q2.G@45.885,-32.202 ccw(c45.458,-32.629) 45.458,-32.025 ccw(c45.458,-31.421) Q2.G@45.885,-31.848 ; Q2.G@46.161,-32.025 R12.1@44.798,-32.025 ; 44.448,-31.675 R12.1@44.448,-32.275 44.698,-32.025 R12.1@44.798,-32.025 ; 44.448,-31.675 R12.1@44.798,-32.025
G2: Q3.G R8.2 R11.1 | length 5.6
  Bottom Layer w0.6: R8.2@33.198,-26.575 33.198,-26.175 ; R11.1@33.198,-25.275 33.198,-26.175 ; R8.2@33.308,-26.61 cw(c34.601,-27.903) Q3.G@34.601,-26.075 ; Q3.G@34.636,-26.287 ccw(c34.124,-26.799) 34.124,-26.075 ccw(c34.124,-25.351) Q3.G@34.636,-25.863 ; Q3.G@34.898,-26.075 33.298,-26.075 33.198,-26.175
GATEH: 
GATEL: 
GND3: 
NetBD1: C102.1 D108.1 L101.1 T101.1 | length 0.1
  Top Layer w1.5: L101.1@81.191,33.4 L101.1@81.272,33.319
  other v1: 57.45,16.2 57.45,17.65 59.4,29.4 59.2,30.2 79.8,32.95 79.8,33.95
NetBD101_1: BD1.3 BD2.3 C101.2 EMC.6 L101.0 pad.2@97.15,33.125 | length 30.3
  Bottom Layer w0.5: pad.2@97,33.225 100.175,33.225 BD2.3@101.25,32.15
  Bottom Layer w1.5: L101.0@80.797,27.203 L101.0@80.797,27.319 ; C101.2@85.75,23.95 86.175,23.525 86.45,23.8 86.45,29.4 EMC.6@90.15,33.1 ; BD2.3@101.25,31.45 101.25,31.1 103.65,28.7 109.5,28.7 111,30.2 BD1.3@111,32.125
  other v1: 96.4,32.75 98,33 96.4,33.6 98,33.65
NetBD101_2: BD1.1 BD1.2 TF101.0
  other v2: 113.625,19.675 114.9,19.675 116.2,19.7 113.625,20.625 114.9,20.625 116.175,20.65 113.625,21.575 114.9,21.575 112.475,21.6 114.5,22.7 113.3,22.75
NetBD101_3: BD2.1 BD2.2 EMC.4 pad.2@97.15,19.25 R120.2 TF101.3 | length 3.9
  Bottom Layer w0.4: R120.2@86.65,18.9 89.75,18.9 EMC.4@90.075,19.225 ; EMC.4@89.325,20.075 EMC.4@89.675,20.075
  other v1: 105.2,21.6 102.55,21.65 103.45,21.65 104.35,21.65
  other v2: 105.675,20.125 106.75,20.125 100.925,20.5 101.9,20.5
NetBD101_4: BD1.4 BD2.4 C101.1 C102.2 EMC.5 pad.2@97.15,26.75 R109.2 R110.1 | length 42.2
  Top Layer w1.5: C102.2@70.875,30.025 70.875,28.775 75.85,23.8 C101.1@76.1,23.8 ; 73.75,11.4 73.75,21.45 C101.1@76.1,23.8 ; EMC.5@90.1,26.725 89.025,27.8 85.6,27.8 81.6,23.8 C101.1@76.1,23.8
  Bottom Layer w0.4: R110.1@70.85,9.325 73.575,9.325 R109.2@73.85,9.6
  Bottom Layer w0.5: EMC.5@90.022,26.725 EMC.5@90.022,27.248 ; BD2.4@106.175,31.45 BD2.4@106.175,32.025
  other v1: 71.9,9.15 71.9,10 71.7,10.8 72.5,10.8 73.35,10.8 74.25,10.8 75.15,10.8 71.7,11.65 72.5,11.65 73.35,11.65 74.25,11.65 75.15,11.65 74.9,24.65 75.65,25.05 91.8,25.4 91.75,26.25 96.45,26.3 97.95,26.75 91.8,27.15 96.45,27.35 91.8,28.05 71.4,28.9 72,29.5
  other v2: 114.875,31.425 117.475,31.475 105.05,31.5 107.475,31.525 114.825,32.4 117.475,32.45 107.45,32.475 105.1,32.525 114.85,33.375 117.475,33.425 105.1,33.475 107.45,33.525
NetC101_1: C1.1 C2.1 C105.2 C130.1 C131.1 D102.5D D102.6D D102.7D D102.8D D102.9D D108.2 EC1.1 EC2.1 EC3.1 LLC.2 pad.2@51.92,-19.95 Q2.D R13.1 R102.2 | length 48.2
  Bottom Layer w0.4: R102.2@27.85,7.6 25.75,5.5 25.75,-2 27.4,-3.65 EC3.1@35.1,-3.65
  Bottom Layer w1.5: EC3.1@35.4,-3.95 46.1,-3.95 EC2.1@46.35,-3.7 ; LLC.2@50.05,0 EC2.1@46.35,-3.7 ; EC1.1@56.8,-3.8 46.45,-3.8 EC2.1@46.35,-3.7 ; D102.9D@63.55,7.54 D102.9D@64.2,6.89
  other v1: 51.148,-39.325 51.998,-39.325 52.848,-39.325 53.698,-39.325 54.548,-39.325 55.398,-39.325 56.248,-39.325 57.098,-39.325 51.148,-38.475 51.998,-38.475 52.848,-38.475 53.698,-38.475 54.548,-38.475 55.398,-38.475 56.248,-38.475 57.098,-38.475 51.148,-37.625 51.998,-37.625 52.848,-37.625 53.698,-37.625 54.548,-37.625 55.398,-37.625 56.248,-37.625 57.098,-37.625 51.148,-36.775 51.998,-36.775 52.848,-36.775 53.698,-36.775 54.548,-36.775 55.398,-36.775 56.248,-36.775 57.098,-36.775 51.148,-35.925 51.998,-35.925 52.848,-35.925 53.698,-35.925 54.548,-35.925 55.398,-35.925 56.248,-35.925 57.098,-35.925 51.148,-35.075 51.998,-35.075 52.848,-35.075 53.698,-35.075 54.548,-35.075 55.398,-35.075 56.248,-35.075 57.098,-35.075 51.148,-34.225 51.998,-34.225 52.848,-34.225 53.698,-34.225 54.548,-34.225 55.398,-34.225 56.248,-34.225 57.098,-34.225 50.998,-33.375 51.848,-33.375 52.698,-33.375 53.548,-33.375 54.398,-33.375 55.248,-33.375 56.098,-33.375 56.948,-33.375 50.148,-32.525 50.998,-32.525 51.848,-32.525 52.698,-32.525 53.548,-32.525 54.398,-32.525 55.248,-32.525 56.098,-32.525 56.948,-32.525 49.298,-31.675 50.148,-31.675 50.998,-31.675 51.848,-31.675 52.698,-31.675 53.548,-31.675 54.398,-31.675 55.248,-31.675 56.098,-31.675 56.948,-31.675 49.298,-30.825 50.148,-30.825 50.998,-30.825 51.848,-30.825 52.698,-30.825 53.548,-30.825 54.398,-30.825 55.248,-30.825 56.098,-30.825 56.948,-30.825 49.298,-29.975 50.148,-29.975 50.998,-29.975 51.848,-29.975 52.698,-29.975 53.548,-29.975 54.398,-29.975 55.248,-29.975 56.098,-29.975 56.948,-29.975 49.298,-29.125 50.148,-29.125 50.998,-29.125 51.848,-29.125 52.698,-29.125 53.548,-29.125 54.398,-29.125 55.248,-29.125 49.298,-28.275 50.148,-28.275 50.998,-28.275 51.848,-28.275 52.698,-28.275 53.548,-28.275 54.398,-28.275 49.298,-27.425 50.148,-27.425 50.998,-27.425 51.848,-27.425 52.698,-27.425 53.548,-27.425 49.298,-26.575 50.148,-26.575 50.998,-26.575 51.848,-26.575 52.698,-26.575 53.548,-26.575 49.348,-25.725 50.148,-25.725 50.998,-25.725 51.848,-25.725 52.698,-25.725 53.548,-25.725 50.198,-24.875 50.998,-24.875 51.848,-24.875 52.698,-24.875 53.548,-24.875 52.098,-24.025 52.098,-23.175 51.198,-22.325 52.098,-22.325 52.948,-22.325 60.85,4.5 64.7,4.5 63.45,4.55 62.2,4.6 60.85,5.4 61.75,5.4 62.65,5.4 63.55,5.4 64.45,5.4 65.35,5.4 60.85,6.3 61.75,6.3 62.65,6.3 63.55,6.3 64.45,6.3 65.35,6.3 60.85,7.2 61.75,7.2 62.65,7.2 63.55,7.2 64.45,7.2 65.35,7.2 60.85,8.1 61.75,8.1 62.65,8.1 63.55,8.1 64.45,8.1 65.35,8.1 61.75,9 62.65,9 63.55,9 64.45,9 65.35,9
  other v3: 51.5,-20.575 52.3,-20.575 51.3,-19.975 52.55,-19.975 51.55,-19.275 52.42,-19.275
NetC101_2: CG2.2 D102.1S D102.2S D102.3S D102.4G IC101.8 Q4.D T101.2 | length 25.8
  Bottom Layer w0.5: IC101.8@51.007,20.56 61.34,20.56 Q4.D@61.85,20.05
  Bottom Layer w1: CG2.2@61.925,22.65 61.85,22.575 Q4.D@61.85,20.05 Q4.D@61.85,18.05 Q4.D@61.85,16.05 Q4.D@61.85,14.05 61.85,11.2 D102.4G@65.15,11.2
NetC104_2: 
NetC107_2: C107.2 R110.2 R119.1 | length 32
  MidLayer1 w0.4: v1(68.55,25.6) 70.85,23.3 v1(70.85,6.55)
  Bottom Layer w0.3: R119.1@59.025,26.85 64.1,26.85 65.25,25.7 68.45,25.7 v1(68.55,25.6)
  Bottom Layer w0.4: R110.2@70.85,7.475 v1(70.85,6.55) 70.85,5.625 C107.2@70.9,5.575
NetC108_1: C108.1 IC101.11 L102.1 LLC.4 pad.2@41.945,-19.95 Q2.S Q3.D R7.1 R14.1 | length 36
  MidLayer1 w0.6: L102.1@42.3,4 42.3,8.1 46.95,12.75 46.95,18.9 43.8,22.05 v1(43.8,22.3)
  MidLayer1 w1.5: LLC.4@39.697,0.598 39.697,1.597 42.1,4 L102.1@42.3,4
  Bottom Layer w0.4: C108.1@43.05,21.95 43.45,21.95 44.6,23.1 IC101.11@45.419,23.1
  Bottom Layer w0.6: R7.1@44.448,-29.375 R7.1@44.648,-29.375 ; Q2.S@45.985,-29.827 cw(c45.773,-28.25) R7.1@44.648,-29.375 ; Q2.S@46.161,-30.025 45.298,-30.025 R7.1@44.648,-29.375
  Bottom Layer w1.5: 39.697,1.75 39.697,2.097 41.425,3.825 L102.1@42.2,3.825
  other v1: 43.698,-27.575 44.498,-27.575 45.298,-27.575 43.698,-26.725 44.498,-26.725 45.298,-26.725 43.698,-25.875 44.498,-25.875 45.298,-25.875
  other v3: 42.52,-20.75 41.27,-20.725 42.52,-20 41.27,-19.975 42.52,-19.25 41.27,-19.225
NetC108_2: C108.2 D106.2 IC101.10 | length 12.1
  Bottom Layer w0.4: C108.2@40.8,21.85 41.85,20.8 43.6,20.8 44.63,21.83 IC101.10@45.419,21.83 46.82,21.83 47.65,21 D106.2@47.65,18.2 ; 47.65,18.45 D106.2@48.5,17.6
NetC114_1: C114.1 C115.1 C118.2 R122.1 T102.1 | length 21.5
  Bottom Layer w0.4: C118.2@29.797,13.823 28.15,15.47 28.15,22.85 30.25,24.95 31.3,24.95 C115.1@31.6,24.65
  Bottom Layer w1: C118.2@29.797,13.823 32.673,13.823 34.997,16.147 T102.1@34.997,17.349
NetC114_2: C114.2 C120.2 C121.2 IC101.14 R121.2 R124.2 | length 19.4
  Bottom Layer w0.3: R124.2@38.925,24.75 39.588,24.75 40.188,25.35 42.325,25.35 C121.2@43.125,26.15 C120.2@43.125,27.75 C120.2@43.4,27.75 ; IC101.14@45.419,26.91 44.59,26.91 43.9,27.6 ; C120.2@43.4,27.75 43.75,27.75 43.9,27.6 ; C120.2@43.4,27.75 43.55,27.6 43.9,27.6
  Bottom Layer w0.4: C114.2@31.55,18.8 32.9,20.15 34.35,20.15 36.125,21.925 36.125,21.95 R124.2@38.925,24.75
NetC115_2: C115.2 C116.1 C117.2 R126.2 | length 9.8
  Bottom Layer w0.3: C115.2@35.1,24.65 36.15,25.7 37.549,25.7 38.174,26.326 ; C116.1@41.275,29.35 40.025,28.1 C117.2@38.875,28.1 R126.2@38.875,26.5 ; 38.174,26.326 38.349,26.5 R126.2@38.875,26.5 ; 38.174,26.326 38.701,26.326 R126.2@38.875,26.5
NetC122_2: C122.2 IC101.3 R119.2 | length 7.3
  Bottom Layer w0.4: IC101.3@51.007,26.91 52.165,26.91 C122.2@53.525,25.55 54.375,26.4 56.725,26.4 R119.2@57.175,26.85
NetC123_2: C123.2 IC101.2 R114.1 R125.2 | length 23.6
  MidLayer1 w0.4: v1(35.8,27.6) 36.5,28.3 52,28.3 v1(52.7,27.6)
  Bottom Layer w0.4: R114.1@34.95,27.6 v1(35.8,27.6) ; IC101.2@51.007,28.18 51.93,28.18 52.6,28.85 C123.2@53.525,28.85 R125.2@53.525,27.3 ; v1(52.7,27.6) 53.05,27.25 R125.2@53.525,27.25
NetC124_2: C124.2 D111.K R129.2 | length 3.6
  Bottom Layer w0.4: D111.K@51.8,33.48 53.205,33.48 R129.2@53.525,33.8 C124.2@53.525,32.05
NetC201_1: 
NetC203_1: 
NetC205_1: 
NetC205_2: C205.2 R206.1 | length 1.6
  Bottom Layer w0.3: C205.2@56.075,47.25 R206.1@56.075,48.85
NetC206_2: 
NetC207_2: R206.2 R209.2 R210.2 R212.2 U202.1 | length 6.8
  Bottom Layer w0.3: U202.1@52.2,47.5 52.225,47.525 R210.2@52.225,49 R212.2@52.225,50.5 ; R210.2@52.2,48.75 54.125,48.75 R206.2@54.225,48.85 R209.2@54.225,50.55
NetC208_2: 
NetC210_1: 
NetC211_1: 
NetCL: 
NetCN: 
NetCN101_L: F101.2 pad.0@116.4,4.05 | length 3.4
  Bottom Layer w1.5: F101.2@116.15,0.825 116.15,3.95 pad.0@116.35,4.15
NetCN101_N: pad.0@116.35,10.05 TF102.1 | length 6.3
  Bottom Layer w1.5: TF102.1@110.9,8.55 112.5,8.55 114,10.05 pad.0@116.2,10.05 ; pad.0@116.35,10.05 pad.0@116.2,10.05 ; pad.0@116.35,10.2 pad.0@116.2,10.05
NetCX101_1: CX101.1 TF101.1 TF102.4 | length 15.3
  Bottom Layer w1.5: CX101.1@102.35,10.15 103.95,8.55 TF102.4@106.1,8.55 ; CX101.1@102.45,10.45 106.6,10.45 110.025,13.875 TF101.1@111.875,13.875
NetCX101_2: CX101.2 CY102.2 EMC.3 pad.2@97.15,12.675 TF101.2 TF102.3 | length 17.4
  Top Layer w0.6: EMC.3@89.45,12.65 EMC.3@90.1,12.65
  Bottom Layer w1: CY102.2@74.297,33.673 75.9,32.07 75.9,29.9
  Bottom Layer w1.5: pad.2@97.15,12.675 99.375,12.675 99.5,12.8 100.575,13.875 TF101.2@103.875,13.875 ; CX101.2@102.15,0.35 103.1,0.35 TF102.3@106.05,3.3
  other v1: 96.5,12.25 96.5,13.15 75.6,29.05 76.45,29.05 75.6,29.9 76.45,29.9
NetD103_1: D1.2 R2.1 R12.2 | length 5.5
  Bottom Layer w0.6: D1.2@44.448,-35.675 44.448,-34.575 ; 44.448,-35.071 ccw(c45.102,-35.071) D1.2@44.639,-35.534 ; R12.2@44.558,-33.84 ccw(c45.247,-33.151) 45.247,-34.125 ; 45.298,-34.125 44.898,-34.125 ; R2.1@45.748,-34.125 44.898,-34.125 ; 44.448,-34.575 44.898,-34.125 ; 44.448,-34.575 R12.2@44.448,-33.875 44.698,-34.125 44.898,-34.125
NetD103_2: D1.1 R1.1 | length 3.7
  Bottom Layer w0.6: D1.1@47.048,-35.675 47.648,-35.675 48.398,-36.425 R1.1@48.698,-36.425 ; D1.1@47.198,-35.875 cw(c47.198,-37.444) R1.1@48.308,-36.335 ; 48.154,-36.181 ccw(c48.623,-35.711) R1.1@48.623,-36.375
NetD104_1: 
NetD104_2: 
NetD105_1: D4.2 R10.1 R11.2 | length 7.1
  Bottom Layer w0.6: R11.2@33.198,-23.675 33.898,-23.675 ; 33.832,-23.675 cw(c33.832,-24.841) D4.2@34.657,-24.016 ; D4.2@34.898,-23.875 34.698,-23.675 34.248,-23.675 ; D4.2@34.922,-23.718 cw(c36.025,-22.325) R10.1@34.248,-22.325 34.248,-23.325 ; 33.898,-23.675 34.248,-23.325 ; 33.898,-23.675 34.248,-23.675 ; 34.248,-23.675 cw(c34.248,-24.053) 34.608,-23.937 ccw(c34.248,-24.053) 34.248,-23.675 ; 34.248,-23.675 34.248,-23.325
NetD105_2: D4.1 R9.1 | length 3
  Bottom Layer w0.5: R9.1@38.748,-22.475 R9.1@38.748,-22.325
  Bottom Layer w0.6: D4.1@37.348,-23.875 R9.1@38.748,-22.475 ; D4.1@37.798,-23.875 cw(c38.884,-23.875) 38.116,-23.107
NetD106_1: D106.1 IC101.6 LLC.5 pad.2@35.77,-19.95 R9.2 R10.2 | length 46.7
  Top Layer w0.5: v1(49.75,23.1) 49.5,22.85 49.5,19.75 v1@51.55,17.7
  MidLayer1 w0.6: v1(46.15,6.55) 46.15,6.85 51.55,12.25 v1@51.55,17.55
  Bottom Layer w0.6: LLC.5@33.522,0.598 33.522,5.372 34.7,6.55 v1(46.15,6.55) ; pad.2@35.24,-20.68 cw(c33.771,-22.149) R10.2@35.848,-22.149 ; pad.2@35.77,-19.95 35.848,-20.028 R10.2@35.848,-22.325 R9.2@37.148,-22.325 ; 35.848,-21.772 cw(c37.392,-21.772) pad.2@36.3,-20.68 ; v1(49.75,23.1) IC101.6@51.007,23.1 ; v1(51.55,17.65) 52.85,17.65 D106.1@52.9,17.6
NetD107_1: R117.1 T102.4 | length 3.8
  Bottom Layer w0.5: T102.4@44.897,17.349 45.022,17.224 45.022,15.598 46.047,14.573 R117.1@46.047,14.073
NetD107_2: D107.1 R117.2 | length 4.4
  Bottom Layer w0.6: R117.2@46.55,10.9 46.55,11.3 49,13.75 D107.1@49,14.3
NetD108_1: 
NetD109_1: 
NetD111_1: C125.2 D111.A IC101.1 R123.2 | length 12.4
  Bottom Layer w0.3: C125.2@53.525,30.45 54.45,31.375 54.45,32.7 54.65,32.9 58.3,32.9 R123.2@59.15,33.75
  Bottom Layer w0.4: D111.A@51.8,31.25 51.8,29.9 ; C125.2@53.525,30.45 53.15,30.45 52.325,29.625 ; 51.8,29.9 51.8,29.5 51.75,29.45 52.15,29.45 52.325,29.625 ; 51.8,29.9 52.075,29.625 52.325,29.625
NetF101_2: F101.1 TF102.2 | length 2.8
  Bottom Layer w1.5: F101.1@110.65,0.7 110.65,3 TF102.2@111,3.35
NetIC101_5: DA1.2 IC101.5 RG4.2 | length 30.9
  Bottom Layer w0.4: IC101.5@51.007,24.37 51.93,24.37 52.65,23.65 58.6,23.65 60.35,25.4 63.25,25.4 64.55,24.1 69,24.1 72.95,20.15 72.95,18.3 ; RG4.2@72.95,15.975 72.95,17.25 ; 72.95,17.25 72.95,18.3 ; 72.95,17.25 DA1.2@72.4,17.8 72.45,17.8 72.95,18.3
NetIC101_8: 
NetIC101_9: IC101.9 LLC.3 pad.2@46.42,-19.95 R1.2 R2.2 | length 47
  Top Layer w0.6: pad.2@45.89,-20.68 cw(c44.18,-22.39) 46.598,-22.39 ; pad.2@46.42,-19.95 46.598,-20.128 46.598,-32.725 v1(48.048,-34.175) ; 46.598,-21.531 cw(c47.801,-21.531) pad.2@46.95,-20.68
  MidLayer1 w0.6: LLC.3@43.35,1.2 43.35,1.5 44,2.15 ; LLC.3@44.172,0.598 43.752,0.598 44,0.847 44,2.15 ; LLC.3@44.85,1.3 44,2.15 ; v1(46.6,20.6) 46.7,20.6 47.85,19.45 47.85,12.2 44,8.35 44,2.15
  Bottom Layer w0.4: IC101.9@45.419,20.56 v1@46.6,20.56 ; pad.2@45.975,-20.395 pad.2@46.42,-19.95 pad.2@46.875,-20.405
  Bottom Layer w0.6: R2.2@47.348,-34.125 47.998,-34.125 R1.2@48.698,-34.825
NetIC101_16: C119.1 IC101.16 U102.4 | length 4.7
  Bottom Layer w0.4: C119.1@44.625,31.25 U102.4@46.538,33.162 ; C119.1@44.65,31 44.65,30 45.2,29.45 IC101.16@45.419,29.45
NetL102_2: L102.3 T102.2 | length 9.1
  Top Layer w1: L102.3@38.213,12.858 38.297,12.942 T102.2@38.297,17.349
  Bottom Layer w1: L102.3@38.213,12.858 38.297,12.942 T102.2@38.297,17.349
NetQ201_2: Q201.4G U201.1GDB | length 3.6
  Bottom Layer w0.6: Q201.4G@34.51,45.25 34.51,47.01 35.588,48.088 U201.1GDB@35.886,48.088
NetQ201_4: Q202.4G U201.8GDA | length 3.8
  Bottom Layer w0.6: Q202.4G@39.86,45.2 39.86,46.96 40.987,48.087 U201.8GDA@41.474,48.087
NetQ201_5: pad.3@36.45,36.95 Q202.5D Q202.6D Q202.7D Q202.8D Q202.9D R207.1 R207.2 U201.6DSA | length 13.9
  MidLayer1 w0.5: v1(39.95,49.35) 41.85,47.45 41.85,45 41,44.15 v1(40.9,44.15)
  Bottom Layer w0.5: Q202.9D@37.95,41.54 39.135,42.725 R207.1@41.55,42.725 ; v1(39.95,49.35) 39.95,50.2 40.377,50.627 U201.6DSA@41.473,50.627 ; v1(40.9,44.15) 41.325,44.575 R207.2@41.55,44.575
  other v1: 38.45,37.6 36.1,38.45 36.9,38.45 37.75,38.45 38.6,38.45 39.45,38.45 36.1,39.35 36.9,39.35 37.75,39.35 38.6,39.35 39.45,39.35 40.65,39.9 36.1,40.25 36.95,40.25 37.85,40.25 38.75,40.25 39.65,40.25 40.65,40.8 36.1,41.15 36.95,41.15 37.85,41.15 38.75,41.15 39.65,41.15 40.65,41.7 36.1,42.05 36.95,42.05 37.85,42.05 38.75,42.05 39.65,42.05 40.65,42.6 36.1,42.95 37,42.95 37.9,42.95 38.8,42.95 39.65,42.95
NetQ201_7: pad.3@32.05,36.9 Q201.5D Q201.6D Q201.7D Q201.8D Q201.9D R208.1 R208.2 U201.3DSB | length 14.6
  MidLayer1 w0.5: v1(29.45,45.4) 29.523,45.4 33.473,49.35 v1(34.3,49.35)
  Bottom Layer w0.5: R208.1@29,42.775 31.415,42.775 Q201.9D@32.6,41.59 ; R208.2@29,44.625 29,44.95 v1(29.45,45.4) ; v1(34.3,49.35) 34.3,49.7 35.227,50.627 U201.3DSB@35.886,50.627
  Bottom Layer w1.5: Q201.9D@32.05,41.04 Q201.9D@32.6,41.59
  other v1: 33.8,36.5 30,36.65 29.95,37.6 33.8,37.8 30.8,38.5 31.6,38.5 32.45,38.5 33.3,38.5 29.95,38.55 30.8,39.4 31.6,39.4 32.45,39.4 33.3,39.4 34.15,39.4 29.95,39.45 30.8,40.3 31.65,40.3 32.55,40.3 33.45,40.3 34.35,40.3 29.95,40.35 30.8,41.2 31.65,41.2 32.55,41.2 33.45,41.2 34.35,41.2 29.95,41.25 30.8,42.1 31.65,42.1 32.55,42.1 33.45,42.1 34.35,42.1 29.95,42.15 30.8,43 31.7,43 32.6,43 33.5,43 34.35,43 29.95,43.05
NetQ202_3: 
NetR102_1: R102.1 R108.2 | length 18.3
  Bottom Layer w0.4: R108.2@26.6,27.65 25.75,26.8 25.75,12.45 27.4,10.8 R102.1@27.85,10.8
NetR108_1: R108.1 R114.2 | length 2.1
  Bottom Layer w0.4: R108.1@29.8,27.65 R114.2@31.85,27.65
NetR118_1: R118.1 R123.1 | length 24.3
  Bottom Layer w0.4: R123.1@62.6,33.95 62.6,33.45 64.4,31.65 64.4,29.2 65.9,27.7 69.35,27.7 70.85,26.2 70.85,25.15 77.1,18.9 R118.1@78.3,18.9
NetR121_1: R121.1 R122.2 | length 1.9
  Bottom Layer w0.5: R122.2@31.4,22.3 R121.1@33.3,22.3
NetR129_1: R129.1 R130.1 | length 1.9
  Bottom Layer w0.4: R129.1@55.375,33.8 57.225,33.8 R130.1@57.25,33.825
NetR131_2: R131.2 U102.3 | length 2
  Bottom Layer w0.4: U102.3@49.2,32.876 49.2,32.075 R131.2@50.025,31.25
NetR132_2: 
NetR203_2: 
NetR204_1: 
NetR211_2: 
NetR213_1: R211.2 R213.1 U102.1 | length 9.8
  Bottom Layer w0.3: R211.2@51.275,43.25 50.025,44.5 48.25,44.5 47.47,43.72 ; 47.47,43.72 47.025,43.275 U102.1@46.65,43.275 47.095,43.72 47.47,43.72
  Bottom Layer w0.4: R213.1@43.5,43.275 U102.1@46.65,43.275
NetR214_1: 
NetR215_2: 
NewNet1: 
NewNet001: 
NewNet2: 
NewNet002: 
NewNet3: 
NewNet003: 
NewNet4: 
NewNet5: 
NewNet6: 
NewNet7: 
NewNet8: 
NewNet9: 
NewNet11: 
NewNet12: 
NewNet13: 
NewNet14: 
NewNet15: 
NewNet16: 
NewNet18: 
NewNet19: 
NewNet20: 
NewNet21: 
NewNet22: 
NewNet23: 
NewNet24: 
NewNet25: 
NewNet26: 
NewNet27: 
NewNet28: 
NewNet29: 
NewNet30: 
NewNet33: 
NewNet34: 
NewNet35: 
NewNet36: 
NewNet37: 
NewNet39: 
NewNet40: 
NewNet41: 
NewNet42: 
NewNet43: 
NewNet44: 
NewNet45: 
NewNet46: 
NewNet47: 
NewNet48: 
NewNet49: 
NewNet50: 
NewNet51: 
NewNet52: 
NewNet53: 
NewNet54: 
NewNet55: 
NewNet56: 
NewNet57: 
NewNet58: 
NewNet59: 
NewNet60: 
NewNet61: 
NewNet62: 
NewNet66: 
OPT: C205.1 R211.1 U102.2 U202.3 | length 10.4
  Bottom Layer w0.3: U102.2@49.5,43.275 U102.2@49.15,43.275 49.975,42.45 52.325,42.45 R211.1@53.125,43.25 52.2,44.175 U202.3@52.2,45.6 52.575,45.6 C205.1@54.225,47.25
